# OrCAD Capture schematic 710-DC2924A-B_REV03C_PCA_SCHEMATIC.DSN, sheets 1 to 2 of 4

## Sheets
1 PAGE4: size A
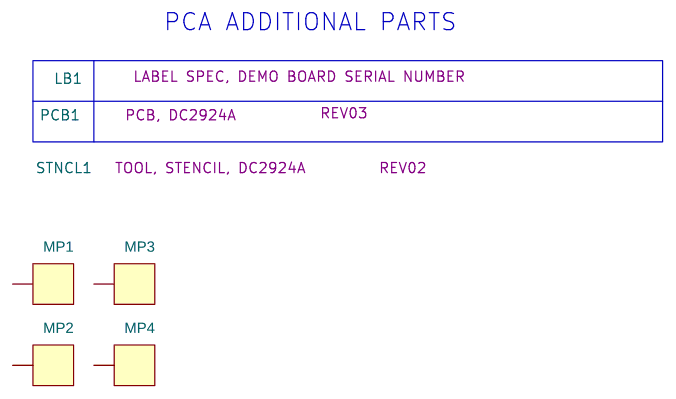
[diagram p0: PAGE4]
2 PAGE1: size Custom; title: DSP6713 SYSTEM; rev: V1.0; company: WITH DIGITAL POWER MANAGEMENT; note: 4 X 30A STEP-DOWN µMODULE SUPPLY WITH PSM
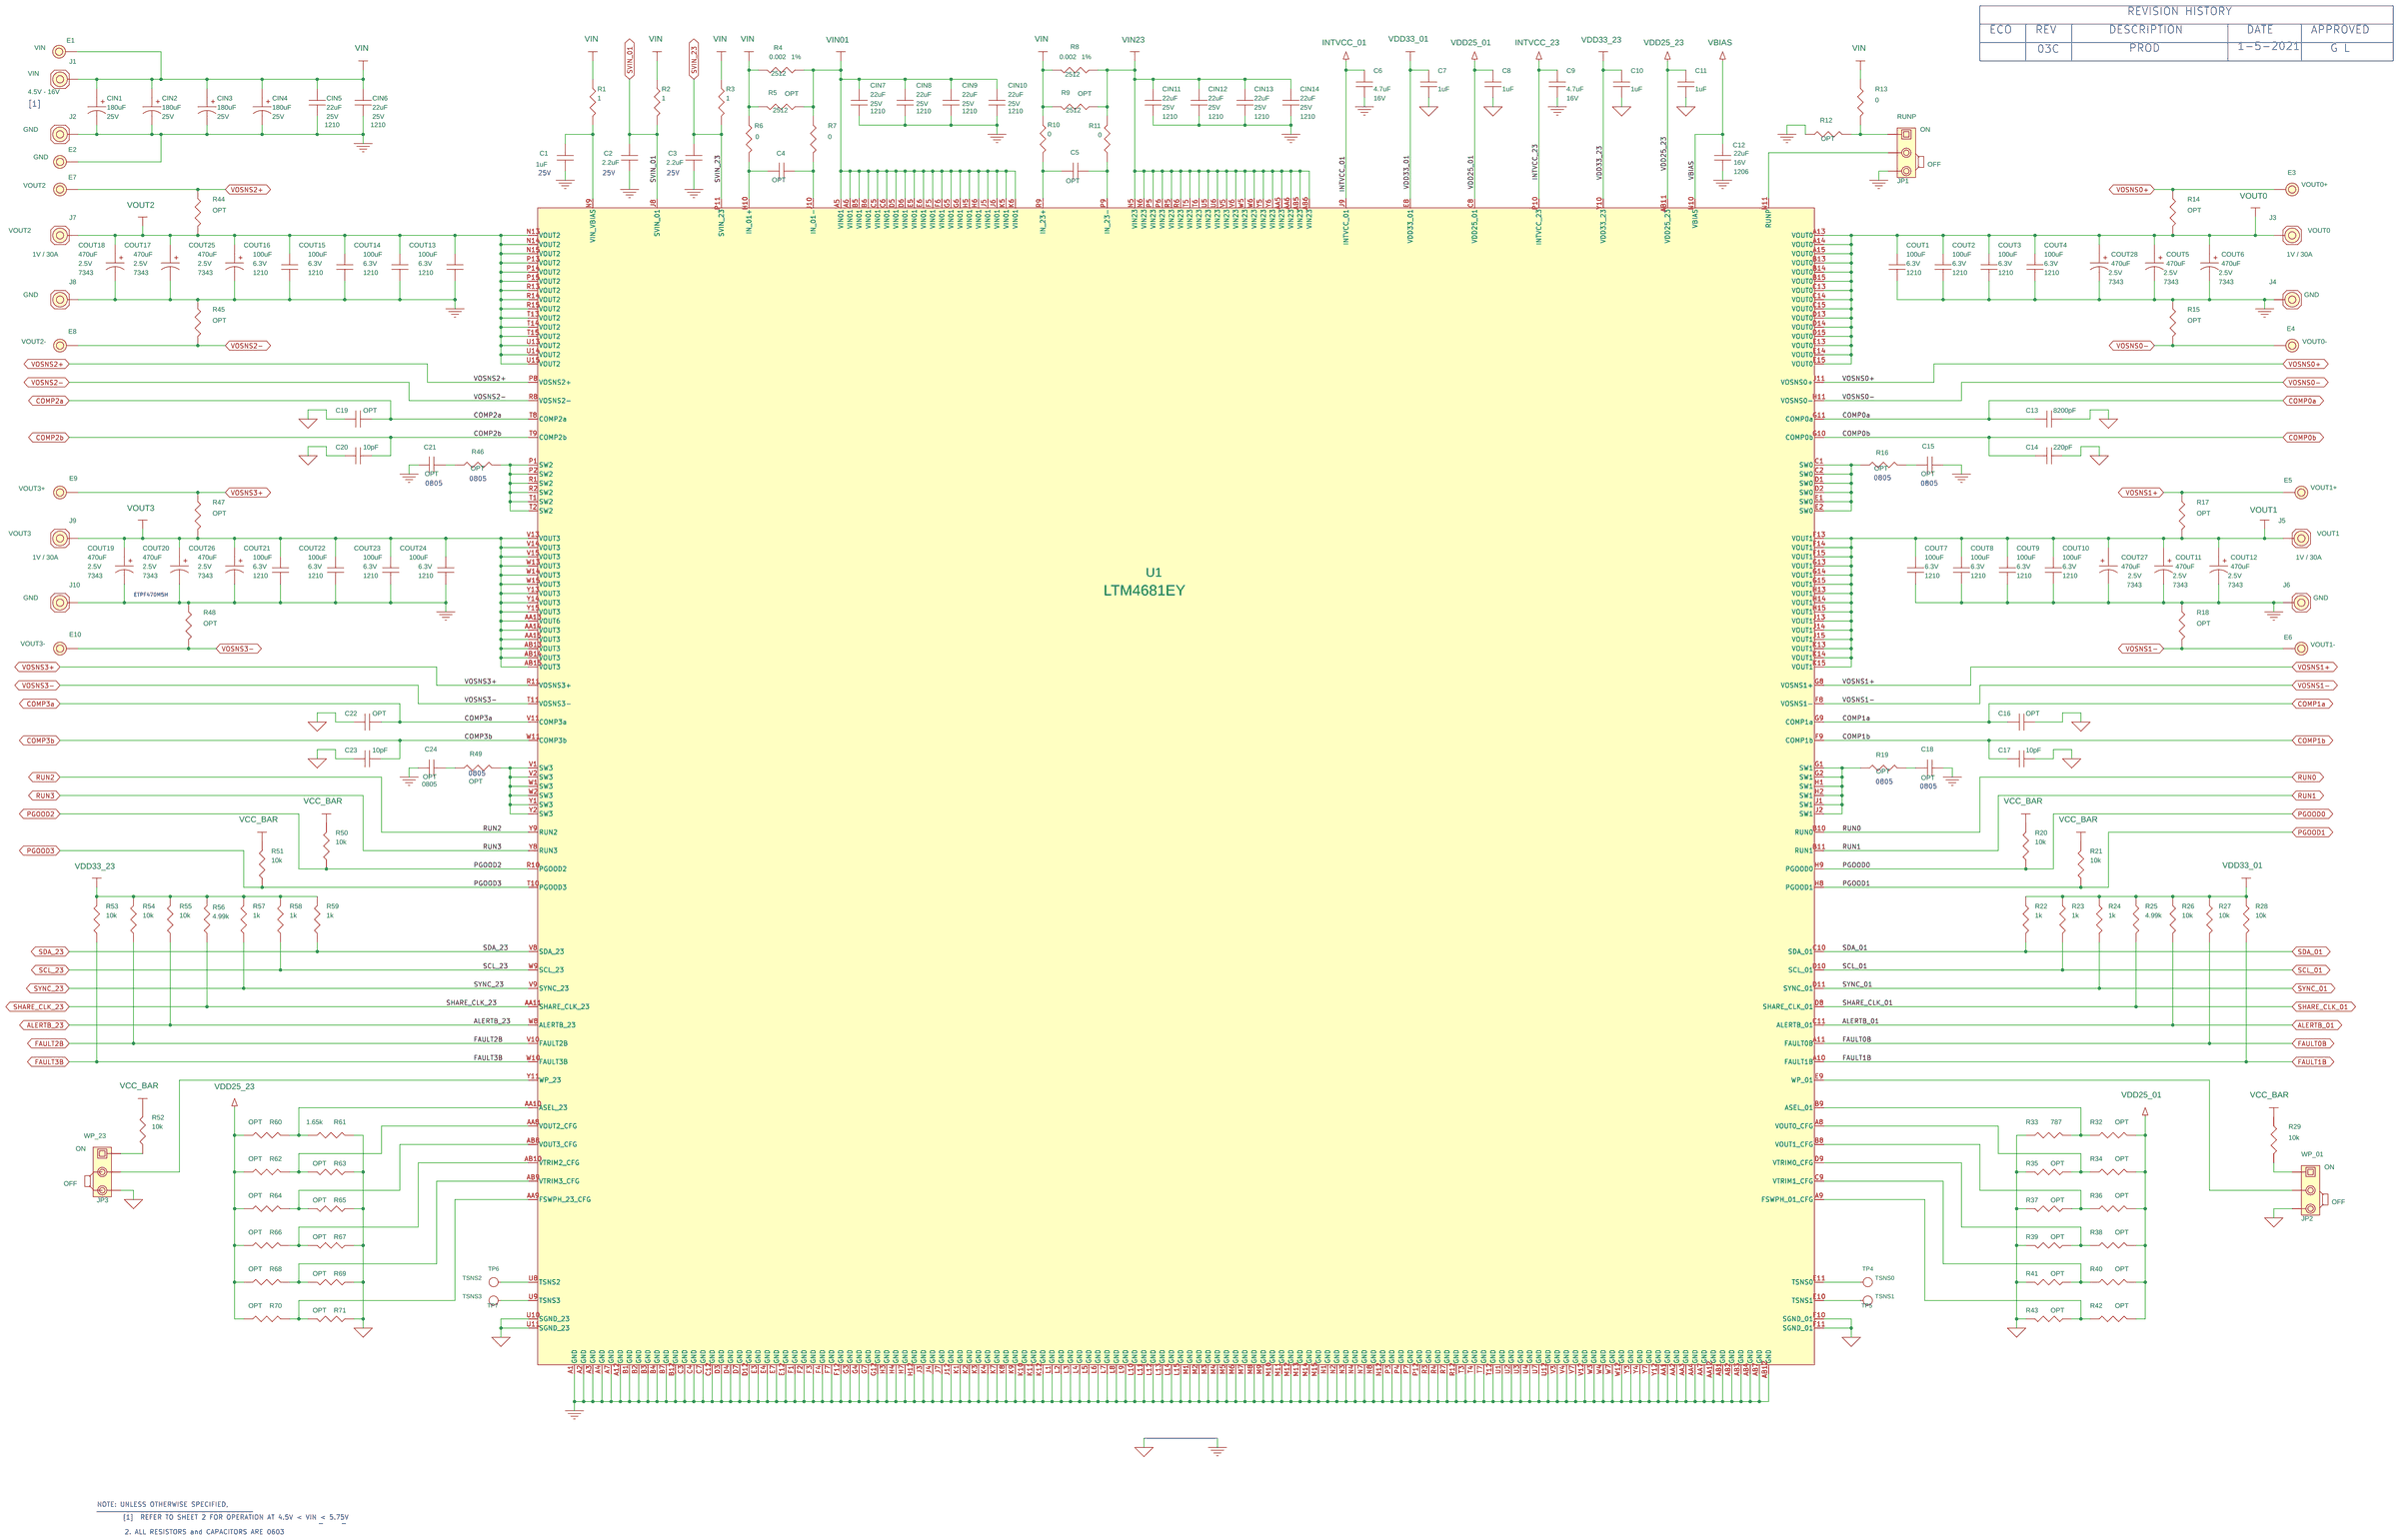
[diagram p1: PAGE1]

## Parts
sheet PAGE1
C1  1uF  [CC0603N]
C2  2.2uF  [CC0603N]
C3  2.2uF  [CC0603N]
C4  OPT  [CC0603N]
C5  OPT  [CC0603N]
C6  4.7uF  [CC0603N]
C7  1uF  [CC0603N]
C8  1uF  [CC0603N]
C9  4.7uF  [CC0603N]
C10  1uF  [CC0603N]
C11  1uF  [CC0603N]
C12  22uF  [CC1206N]
C13  8200pF  [CC0603N]
C14  220pF  [CC0603N]
C15  OPT  [CC0805N]
C16  OPT  [CC0603N]
C17  10pF  [CC0603N]
C18  OPT  [CC0805N]
C19  OPT  [CC0603N]
C20  10pF  [CC0603N]
C21  OPT  [CC0805N]
C22  OPT  [CC0603N]
C23  10pF  [CC0603N]
C24  OPT  [CC0805N]
CIN1  180uF  [PANASONIC_SVPF_8X11.9]
CIN2  180uF  [PANASONIC_SVPF_8X11.9]
CIN3  180uF  [PANASONIC_SVPF_8X11.9]
CIN4  180uF  [PANASONIC_SVPF_8X11.9]
CIN5  22uF  [CC1210N]
CIN6  22uF  [CC1210N]
CIN7  22uF  [CC1210N]
CIN8  22uF  [CC1210N]
CIN9  22uF  [CC1210N]
CIN10  22uF  [CC1210N]
CIN11  22uF  [CC1210N]
CIN12  22uF  [CC1210N]
CIN13  22uF  [CC1210N]
CIN14  22uF  [CC1210N]
COUT1  100uF  [CC1210N]
COUT2  100uF  [CC1210N]
COUT3  100uF  [CC1210N]
COUT4  100uF  [CC1210N]
COUT5  470uF  [CAPMP7343N]
COUT6  470uF  [CAPMP7343N]
COUT7  100uF  [CC1210N]
COUT8  100uF  [CC1210N]
COUT9  100uF  [CC1210N]
COUT10  100uF  [CC1210N]
COUT11  470uF  [CAPMP7343N]
COUT12  470uF  [CAPMP7343N]
COUT13  100uF  [CC1210N]
COUT14  100uF  [CC1210N]
COUT15  100uF  [CC1210N]
COUT16  100uF  [CC1210N]
COUT17  470uF  [CAPMP7343N]
COUT18  470uF  [CAPMP7343N]
COUT19  470uF  [CAPMP7343N]
COUT20  470uF  [CAPMP7343N]
COUT21  100uF  [CC1210N]
COUT22  100uF  [CC1210N]
COUT23  100uF  [CC1210N]
COUT24  100uF  [CC1210N]
COUT25  470uF  [CAPMP7343N]
COUT26  470uF  [CAPMP7343N]
COUT27  470uF  [CAPMP7343N]
COUT28  470uF  [CAPMP7343N]
E1  TEST POINT  [MILLMAX2501]
E2  TEST POINT  [MILLMAX2501]
E3  TEST POINT  [MILLMAX2501]
E4  TEST POINT  [MILLMAX2501]
E5  TEST POINT  [MILLMAX2501]
E6  TEST POINT  [MILLMAX2501]
E7  TEST POINT  [MILLMAX2501]
E8  TEST POINT  [MILLMAX2501]
E9  TEST POINT  [MILLMAX2501]
E10  TEST POINT  [MILLMAX2501]
J1  STUD,#10-32  [PENN-KFH-032]
J2  STUD,#10-32  [PENN-KFH-032]
J3  STUD,#10-32  [PENN-KFH-032]
J4  STUD,#10-32  [PENN-KFH-032]
J5  STUD,#10-32  [PENN-KFH-032]
J6  STUD,#10-32  [PENN-KFH-032]
J7  STUD,#10-32  [PENN-KFH-032]
J8  STUD,#10-32  [PENN-KFH-032]
J9  STUD,#10-32  [PENN-KFH-032]
J10  STUD,#10-32  [PENN-KFH-032]
JP1  HDR  [HD1X3-079]
JP2  HDR  [HD1X3-079]
JP3  HDR  [HD1X3-079]
R1  1  [CR0603N]
R2  1  [CR0603N]
R3  1  [CR0603N]
R4  0.002  [VISHAY-WSL2512_T87]
R5  OPT  [CR2512N]
R6  0  [CR0603N]
R7  0  [CR0603N]
R8  0.002  [VISHAY-WSL2512_T87]
R9  OPT  [CR2512N]
R10  0  [CR0603N]
R11  0  [CR0603N]
R12  OPT  [CR0603N]
R13  0  [CR0603N]
R14  OPT  [CR0603N]
R15  OPT  [CR0603N]
R16  OPT  [CR0805N]
R17  OPT  [CR0603N]
R18  OPT  [CR0603N]
R19  OPT  [CR0805N]
R20  10k  [CR0603N]
R21  10k  [CR0603N]
R22  1k  [CR0603N]
R23  1k  [CR0603N]
R24  1k  [CR0603N]
R25  4.99k  [CR0603N]
R26  10k  [CR0603N]
R27  10k  [CR0603N]
R28  10k  [CR0603N]
R29  10k  [CR0603N]
R32  OPT  [CR0603N]
R33  787  [CR0603N]
R34  OPT  [CR0603N]
R35  OPT  [CR0603N]
R36  OPT  [CR0603N]
R37  OPT  [CR0603N]
R38  OPT  [CR0603N]
R39  OPT  [CR0603N]
R40  OPT  [CR0603N]
R41  OPT  [CR0603N]
R42  OPT  [CR0603N]
R43  OPT  [CR0603N]
R44  OPT  [CR0603N]
R45  OPT  [CR0603N]
R46  OPT  [CR0805N]
R47  OPT  [CR0603N]
R48  OPT  [CR0603N]
R49  OPT  [CR0805N]
R50  10k  [CR0603N]
R51  10k  [CR0603N]
R52  10k  [CR0603N]
R53  10k  [CR0603N]
R54  10k  [CR0603N]
R55  10k  [CR0603N]
R56  4.99k  [CR0603N]
R57  1k  [CR0603N]
R58  1k  [CR0603N]
R59  1k  [CR0603N]
R60  OPT  [CR0603N]
R61  1.65k  [CR0603N]
R62  OPT  [CR0603N]
R63  OPT  [CR0603N]
R64  OPT  [CR0603N]
R65  OPT  [CR0603N]
R66  OPT  [CR0603N]
R67  OPT  [CR0603N]
R68  OPT  [CR0603N]
R69  OPT  [CR0603N]
R70  OPT  [CR0603N]
R71  OPT  [CR0603N]
TP4  TSNS0  [TP-.762MM]
TP5  TSNS1  [TP-.762MM]
TP6  TSNS2  [TP-.762MM]
TP7  TSNS3  [TP-.762MM]
U1  LTM4681EY  [LTC-BGA-330-4681Y]
XJP1  SHUNT
XJP2  SHUNT
XJP3  SHUNT
sheet PAGE4
LB1  LABEL  [895-0154_REV01]
MP1  STANDOFF  [KEYSTONE_8829-8834]
MP2  STANDOFF  [KEYSTONE_8829-8834]
MP3  STANDOFF  [KEYSTONE_8829-8834]
MP4  STANDOFF  [KEYSTONE_8829-8834]
PCB1  PCB, DC2924A
STNCL1  TOOL, STENCIL, DC2924A

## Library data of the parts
C1 C7 C8 C10 C11 = CAP: CAP.,1uF,X7R,25V,10%,0603,AEC-Q200; CLASS: DISCRETE; Dielectric Type: X7R; FPLIST: CC0603N,CC0603L,CC0603M; Inventory Qty: 53700; Manufacturer: MURATA; Manufacturer PN: GCM188R71E105KA64D; PART_NUMBER: 150-0291; Package Size: 0603; Rated Voltage: 25V; Tolerance: 10%
C2 C3 = CAP: CAP.,2.2uF,X5R,25V,10%,0603; CLASS: DISCRETE; Dielectric Type: X5R; FPLIST: CC0603N,CC0603L,CC0603M; Inventory Qty: 35022; Manufacturer: MURATA; Manufacturer PN: GRM188R61E225KA12D; PART_NUMBER: 150-3289; Package Size: 0603; Rated Voltage: 25V; Tolerance: 10%
C4 C5 C16 C19 C22 = CAP: CAP., OPTION, 0603; CLASS: DISCRETE; FPLIST: CC0603N,CC0603L,CC0603M; PART_NUMBER: 150-3038; Package Size: 0603; Package Type: SMD
C6 C9 = CAP: CAP.,4.7uF,X5R,16V,10%,0603; CLASS: DISCRETE; Dielectric Type: X5R; FPLIST: CC0603N,CC0603L,CC0603M; Inventory Qty: 44050; Manufacturer: MURATA; Manufacturer PN: GRM188R61C475KAAJD; PART_NUMBER: 150-3182; Package Size: 0603; Rated Voltage: 16V; Tolerance: 10%
C12 = CAP: CAP.,22uF,X5R,16V,10%,1206; CLASS: DISCRETE; Dielectric Type: X5R; FPLIST: CC1206N,CC1206L,CC1206M; Inventory Qty: 6429; Manufacturer: AVX; Manufacturer PN: 1206YD226KAT2A; PART_NUMBER: 150-3044; Package Size: 1206; Rated Voltage: 16V; Tolerance: 10%
C13 = CAP: CAP.,8200pF,X7R,16V,5%,0603; CLASS: DISCRETE; Dielectric Type: X7R; FPLIST: CC0603N,CC0603L,CC0603M; Inventory Qty: 4000; Manufacturer: AVX; Manufacturer PN: 0603YC822JAT2A; PART_NUMBER: 150-1315; Package Size: 0603; Rated Voltage: 16V; Tolerance: 5%
C14 = CAP: CAP.,220pF,X7R,50V,5%,0603; CLASS: DISCRETE; Dielectric Type: X7R; FPLIST: CC0603N,CC0603L,CC0603M; Inventory Qty: 0; Manufacturer: KEMET; Manufacturer PN: C0603C221J5RAC7867; PART_NUMBER: 150-0043; Package Size: 0603; Rated Voltage: 50V; Tolerance: 5%
C15 C18 C21 C24 = CAP: CAP., OPTION, 0805; CLASS: DISCRETE; FPLIST: CC0805N,CC0805L,CC0805M; PART_NUMBER: 150-3036; Package Size: 0805; Package Type: SMD
C17 C20 C23 = CAP: CAP.,10pF,C0G,50V,5%,0603; CLASS: DISCRETE; Dielectric Type: C0G; FPLIST: CC0603N,CC0603L,CC0603M; Inventory Qty: 6220; Manufacturer: AVX; Manufacturer PN: 06035A100JAT2A; PART_NUMBER: 150-0023; Package Size: 0603; Rated Voltage: 50V; Tolerance: 5%
CIN1-CIN4 = CAP_P_ALT: CAP.,180uF,ALUM POLY,OS-CON,25V,20%,8x11.9mm,SMD,RADIAL,E12; CLASS: DISCRETE; Dielectric Type: ALUM POLY,OS-CON; Inventory Qty: 5334; Manufacturer: PANASONIC; Manufacturer PN: 25SVPF180M; PART_NUMBER: 150-2329; Package Size: 8x11.9mm,SMD,RADIAL,E12; Rated Voltage: 25V; Tolerance: 20%
CIN5-CIN14 = CAP: CAP.,22uF,X5R,25V,10%,1210; CLASS: DISCRETE; Dielectric Type: X5R; FPLIST: CC1210N,CC1210L,CC1210M; Inventory Qty: 26336; Manufacturer: KEMET; Manufacturer PN: C1210C226K3PACTU; PART_NUMBER: 150-3033; Package Size: 1210; Package Type: SMD; Rated Voltage: 25V; Tolerance: 10%
COUT1-COUT4 COUT7-COUT10 COUT13-COUT16 COUT21-COUT24 = CAP: CAP.,100uF,X5R,6.3V,20%,1210; CLASS: DISCRETE; Dielectric Type: X5R; FPLIST: CC1210N,CC1210L,CC1210M; Inventory Qty: 50440; Manufacturer: AVX; Manufacturer PN: 12106D107MAT2A; PART_NUMBER: 150-3008; Package Size: 1210; Rated Voltage: 6.3V; Tolerance: 20%
COUT5 COUT6 COUT11 COUT12 COUT17 COUT20 COUT25-COUT28 = CAP_P_ALT: CAP.,470uF,TANT,POSCAP,2.5V,20%,7343,TPF Series; CLASS: DISCRETE; Dielectric Type: TANT,POSCAP; FPLIST: CAPMP7343N,CAPMP7343L,CAPMP7343M; Inventory Qty: 26416; Manufacturer: PANASONIC; Manufacturer PN: ETPF470M5H; PART_NUMBER: 150-2629; Package Size: 7343; Rated Voltage: 2.5V; Tolerance: 20%
COUT18 = CAP_P_ALT: CAP.,470uF,TANT,POSCAP,2.5V,20%,7343,TPF Series; CLASS: DISCRETE; Dielectric Type: TANT,POSCAP; FPLIST: CAPMP7343N,CAPMP7343L,CAPMP7343M; Inventory Qty: 26416; Manufacturer: PANASONIC; Manufacturer PN: ETPF470M5H; PART_FIELD_01: 2.5V; PART_NUMBER: 150-2629; Package Size: 7343; Rated Voltage: 2.5V; Tolerance: 20%
COUT19 = CAP_P_ALT: CAP.,470uF,TANT,POSCAP,2.5V,20%,7343,TPF Series; BOM Notes: COUT1,COUT6=6.3V; CLASS: DISCRETE; Dielectric Type: TANT,POSCAP; FPLIST: CAPMP7343N,CAPMP7343L,CAPMP7343M; Inventory Qty: 26416; Manufacturer: PANASONIC; Manufacturer PN: ETPF470M5H; PART_FIELD_01: 2.5V; PART_NUMBER: 150-2629; Package Size: 7343; Rated Voltage: 2.5V; Tolerance: 20%
E1 = TESTPOINT_.219_MILL-MAX_2501: TEST POINT,TURRET,0.094" MTG. HOLE,PCB 0.062" THK; 9th Part Field: VIN; CLASS: IO; Inventory Qty: 823526; Manufacturer: MILL-MAX; Manufacturer PN: 2501-2-00-80-00-00-07-0; PART_NUMBER: 260-0003
E2 = TESTPOINT_.219_MILL-MAX_2501: TEST POINT,TURRET,0.094" MTG. HOLE,PCB 0.062" THK; 9th Part Field: GND; CLASS: IO; Inventory Qty: 823526; Manufacturer: MILL-MAX; Manufacturer PN: 2501-2-00-80-00-00-07-0; PART_NUMBER: 260-0003
E3 = TESTPOINT_.219_MILL-MAX_2501: TEST POINT,TURRET,0.094" MTG. HOLE,PCB 0.062" THK; 5TH PART FIELD: VOUT0+; CLASS: IO; Inventory Qty: 823526; Manufacturer: MILL-MAX; Manufacturer PN: 2501-2-00-80-00-00-07-0; PART_NUMBER: 260-0003
E4 = TESTPOINT_.219_MILL-MAX_2501: TEST POINT,TURRET,0.094" MTG. HOLE,PCB 0.062" THK; 5TH PART FIELD: VOUT0-; CLASS: IO; Inventory Qty: 823526; Manufacturer: MILL-MAX; Manufacturer PN: 2501-2-00-80-00-00-07-0; PART_NUMBER: 260-0003
E5 = TESTPOINT_.219_MILL-MAX_2501: TEST POINT,TURRET,0.094" MTG. HOLE,PCB 0.062" THK; 9th Part Field: VOUT1+; CLASS: IO; Inventory Qty: 823526; Manufacturer: MILL-MAX; Manufacturer PN: 2501-2-00-80-00-00-07-0; PART_NUMBER: 260-0003
E6 = TESTPOINT_.219_MILL-MAX_2501: TEST POINT,TURRET,0.094" MTG. HOLE,PCB 0.062" THK; 9th Part Field: VOUT1-; CLASS: IO; Inventory Qty: 823526; Manufacturer: MILL-MAX; Manufacturer PN: 2501-2-00-80-00-00-07-0; PART_NUMBER: 260-0003
E7 = TESTPOINT_.219_MILL-MAX_2501: TEST POINT,TURRET,0.094" MTG. HOLE,PCB 0.062" THK; 9th Part Field: VOUT2; CLASS: IO; Inventory Qty: 823526; Manufacturer: MILL-MAX; Manufacturer PN: 2501-2-00-80-00-00-07-0; PART_NUMBER: 260-0003
E8 = TESTPOINT_.219_MILL-MAX_2501: TEST POINT,TURRET,0.094" MTG. HOLE,PCB 0.062" THK; 9th Part Field: VOUT2-; CLASS: IO; Inventory Qty: 823526; Manufacturer: MILL-MAX; Manufacturer PN: 2501-2-00-80-00-00-07-0; PART_NUMBER: 260-0003
E9 = TESTPOINT_.219_MILL-MAX_2501: TEST POINT,TURRET,0.094" MTG. HOLE,PCB 0.062" THK; 9th Part Field: VOUT3+; CLASS: IO; Inventory Qty: 823526; Manufacturer: MILL-MAX; Manufacturer PN: 2501-2-00-80-00-00-07-0; PART_NUMBER: 260-0003
E10 = TESTPOINT_.219_MILL-MAX_2501: TEST POINT,TURRET,0.094" MTG. HOLE,PCB 0.062" THK; 9th Part Field: VOUT3-; CLASS: IO; Inventory Qty: 823526; Manufacturer: MILL-MAX; Manufacturer PN: 2501-2-00-80-00-00-07-0; PART_NUMBER: 260-0003
J1 = PEM-KFH: EVAL BOARD STUD HARDWARE SET, #10-32; 10th Part Field: 4.5V - 16V; 9th Part Field: VIN; CLASS: DISCRETE; Comments: CONSISTS OF QTY(1) STUD, 769-0012; QTY(1) RING LUG, 769-0013;QTY(2) HEX NUT,BRASS,761-0013; QTY(1) WASHER,#10 LOCK, 762-0021; Manufacturer: ANALOG DEVICES; Manufacturer PN: 720-0010; PART_NUMBER: 720-0010
J2 J4 J6 J8 J10 = PEM-KFH: EVAL BOARD STUD HARDWARE SET, #10-32; 9th Part Field: GND; CLASS: DISCRETE; Comments: CONSISTS OF QTY(1) STUD, 769-0012; QTY(1) RING LUG, 769-0013;QTY(2) HEX NUT,BRASS,761-0013; QTY(1) WASHER,#10 LOCK, 762-0021; Manufacturer: ANALOG DEVICES; Manufacturer PN: 720-0010; PART_NUMBER: 720-0010
J3 = PEM-KFH: EVAL BOARD STUD HARDWARE SET, #10-32; 10th Part Field: 1V / 30A; 9th Part Field: VOUT0; CLASS: DISCRETE; Comments: CONSISTS OF QTY(1) STUD, 769-0012; QTY(1) RING LUG, 769-0013;QTY(2) HEX NUT,BRASS,761-0013; QTY(1) WASHER,#10 LOCK, 762-0021; Manufacturer: ANALOG DEVICES; Manufacturer PN: 720-0010; PART_NUMBER: 720-0010
J5 = PEM-KFH: EVAL BOARD STUD HARDWARE SET, #10-32; 10th Part Field: 1V / 30A; 9th Part Field: VOUT1; CLASS: DISCRETE; Comments: CONSISTS OF QTY(1) STUD, 769-0012; QTY(1) RING LUG, 769-0013;QTY(2) HEX NUT,BRASS,761-0013; QTY(1) WASHER,#10 LOCK, 762-0021; Manufacturer: ANALOG DEVICES; Manufacturer PN: 720-0010; PART_NUMBER: 720-0010
J7 = PEM-KFH: EVAL BOARD STUD HARDWARE SET, #10-32; 10th Part Field: 1V / 30A; 9th Part Field: VOUT2; CLASS: DISCRETE; Comments: CONSISTS OF QTY(1) STUD, 769-0012; QTY(1) RING LUG, 769-0013;QTY(2) HEX NUT,BRASS,761-0013; QTY(1) WASHER,#10 LOCK, 762-0021; Manufacturer: ANALOG DEVICES; Manufacturer PN: 720-0010; PART_NUMBER: 720-0010
J9 = PEM-KFH: EVAL BOARD STUD HARDWARE SET, #10-32; 10th Part Field: 1V / 30A; 9th Part Field: VOUT3; CLASS: DISCRETE; Comments: CONSISTS OF QTY(1) STUD, 769-0012; QTY(1) RING LUG, 769-0013;QTY(2) HEX NUT,BRASS,761-0013; QTY(1) WASHER,#10 LOCK, 762-0021; Manufacturer: ANALOG DEVICES; Manufacturer PN: 720-0010; PART_NUMBER: 720-0010
JP1 = 1X3_A: CONN.,HDR,MALE,1x3,2mm,VERT,ST,THT,NO SUBS. ALLOWED; 11th Part Field: OFF; 12th Part Field: RUNP; 9th Part Field: ON; CLASS: IO; Inventory Qty: 28997; Manufacturer: Wurth Elektronik; Manufacturer PN: 62000311121; PART_NUMBER: 250-0639
JP2 = 1X3_A: CONN.,HDR,MALE,1x3,2mm,VERT,ST,THT,NO SUBS. ALLOWED; 11th Part Field: OFF; 12th Part Field: WP_01; 9th Part Field: ON; CLASS: IO; Inventory Qty: 28997; Manufacturer: Wurth Elektronik; Manufacturer PN: 62000311121; PART_NUMBER: 250-0639
JP3 = 1X3_A: CONN.,HDR,MALE,1x3,2mm,VERT,ST,THT,NO SUBS. ALLOWED; 11th Part Field: OFF; 12th Part Field: WP_23; 9th Part Field: ON; CLASS: IO; Inventory Qty: 28997; Manufacturer: Wurth Elektronik; Manufacturer PN: 62000311121; PART_NUMBER: 250-0639
R1-R3 = RES: RES.,1 OHM,1%,1/10W,0603,AEC-Q200; CLASS: DISCRETE; FPLIST: CR0603N,CR0603L,CR0603M; Inventory Qty: 53360; Manufacturer: NIC; Manufacturer PN: NRC06F1R00TRF; PART_NUMBER: 100-0238; Package Size: 0603; Rated Power: 1/10W; Temperature Coefficient: 100ppm/C; Tolerance: 1%
R4 R8 = RES: RES.,0.002 OHM,1%,1W,2512,SENSE; CLASS: DISCRETE; FPLIST: CR2512N,CR2512L,CR2512M; Inventory Qty: 9849; Manufacturer: VISHAY; Manufacturer PN: WSL25122L000FEA; PART_NUMBER: 100-0062; Package Size: 2512; Rated Power: 1W; Temperature Coefficient: 275ppm/C; Tolerance: 1%
R5 R9 = RES: RES., OPTION, 2512; CLASS: DISCRETE; FPLIST: CR2512N,CR2512L,CR2512M,USER_ASSIGNED; PART_NUMBER: 100-2376; Package Size: 2512
R6 R7 R10 R11 R13 = RES: RES.,0 OHM,1/10W,0603,AEC-Q200; CLASS: DISCRETE; FPLIST: CR0603N,CR0603L,CR0603M; Inventory Qty: 700742; Manufacturer: VISHAY; Manufacturer PN: CRCW06030000Z0EA; PART_NUMBER: 100-0009; Package Size: 0603; Rated Power: 1/10W
R12 R14 R15 R17 R18 R32 R34-R45 R47 R48 R60 R62-R71 = RES: RES., OPTION, 0603; CLASS: DISCRETE; FPLIST: CR0603N,CR0603L,CR0603M; PART_NUMBER: 100-2374; Package Size: 0603
R16 R19 R46 R49 = RES: RES., OPTION, 0805; CLASS: DISCRETE; FPLIST: CR0805N,CR0805L,CR0805M; PART_NUMBER: 100-2558; Package Size: 0805
R20 R21 R26-R29 R50-R55 = RES: RES.,10k OHMS,1%,1/10W,0603,AEC-Q200; CLASS: DISCRETE; FPLIST: CR0603N,CR0603L,CR0603M; Inventory Qty: 194448; Manufacturer: VISHAY; Manufacturer PN: CRCW060310K0FKEA; PART_NUMBER: 100-2012; Package Size: 0603; Rated Power: 1/10W; Temperature Coefficient: +/-100ppm/C; Tolerance: 1%
R22-R24 R57-R59 = RES: RES.,1k OHM,1%,1/10W,0603; CLASS: DISCRETE; FPLIST: CR0603N,CR0603L,CR0603M; Inventory Qty: 62420; Manufacturer: VISHAY; Manufacturer PN: CRCW06031K00FKEA; PART_NUMBER: 100-0136; Package Size: 0603; Rated Power: 1/10W; Temperature Coefficient: +/-100ppm; Tolerance: 1%
R25 R56 = RES: RES.,4.99k OHMS,1%,1/10W,0603; CLASS: DISCRETE; FPLIST: CR0603N,CR0603L,CR0603M; Inventory Qty: 72747; Manufacturer: PANASONIC; Manufacturer PN: ERJ3EKF4991V; PART_NUMBER: 100-0121; Package Size: 0603; Rated Power: 1/10W; Temperature Coefficient: 100ppm/C; Tolerance: 1%
R33 = RES: RES.,787 OHMS,1%,1/10W,0603; CLASS: DISCRETE; FPLIST: CR0603N,CR0603L,CR0603M; Inventory Qty: 19395; Manufacturer: NIC; Manufacturer PN: NRC06F7870TRF; PART_NUMBER: 100-2721; Package Size: 0603; Rated Power: 1/10W; Temperature Coefficient: 100ppm/C; Tolerance: 1%
R61 = RES: RES.,1.65k OHMS,1%,1/10W,0603; CLASS: DISCRETE; FPLIST: CR0603N,CR0603L,CR0603M; Inventory Qty: 27055; Manufacturer: NIC; Manufacturer PN: NRC06F1651TRF; PART_NUMBER: 100-2723; Package Size: 0603; Rated Power: 1/10W; Temperature Coefficient: 100ppm/C; Tolerance: 1%
TP4-TP7 = E-100SMT
U1 = LTM4681-BGA: IC,QUAD OUTPUT uMODULE REG.,BGA; CLASS: IC; Inventory Qty: 0; Manufacturer: ANALOG DEVICES; Manufacturer PN: LTM4681EY#PBF; PART_NUMBER: LTM4681EY#PBF; Package Type: BGA
XJP1-XJP3 = SHUNT_2MM: CONN.,SHUNT,FEMALE,2 POS,2mm; CLASS: IO; Inventory Qty: 64675; Manufacturer: Wurth Elektronik; Manufacturer PN: 60800213421; PART_NUMBER: 250-0485
LB1 = BLANK_LABEL: LABEL SPEC, DEMO BOARD SERIAL NUMBER; Inventory Qty: 0; Manufacturer: BRADY; Manufacturer PN: THT-96-717-10; PART_NUMBER: 895-0154
MP1-MP4 = MP-PINNED: STANDOFF,NYLON,SNAP-ON,0.50"; CLASS: DISCRETE; FPLIST: KEYSTONE_8829-8834,KEYSTONE_8833,MTG-8831; Inventory Qty: 214842; Manufacturer: KEYSTONE; Manufacturer PN: 8833; PART_NUMBER: 763-0007
PCB1 = BLANK_PCB_PART: BOM Notes: REV03; CLASS: DISCRETE; Inventory Qty: 0; Manufacturer: ADI APPROVED SUPPLIER; Manufacturer PN: 600-DC2924A; PART_NUMBER: 600-DC2924A
STNCL1 = BLANK_STENCIL_PART: BOM Notes: REV02; CLASS: DISCRETE; Inventory Qty: 0; Manufacturer: ANALOG DEVICES; Manufacturer PN: 830-DC2924A; PART_NUMBER: 830-DC2924A

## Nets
GND: C1.1 C2.1 C3.1 C6.1 C9.1 C12.1 C15.1 C18.1 C21.1 C24.1 CIN1.2 CIN2.2 CIN3.2 CIN4.2 CIN5.1 CIN6.1 CIN7.1 CIN8.1 CIN9.1 CIN10.1 CIN11.1 CIN12.1 CIN13.1 CIN14.1 COUT1.2 COUT2.2 COUT3.2 COUT4.2 COUT5.2 COUT6.2 COUT7.2 COUT8.2 COUT9.2 COUT10.2 COUT11.2 COUT12.2 COUT13.2 COUT14.2 COUT15.2 COUT16.2 COUT17.2 COUT18.2 COUT19.2 COUT20.2 COUT21.2 COUT22.2 COUT23.2 COUT24.2 COUT25.2 COUT26.2 COUT27.2 COUT28.2 E2.1 J2.1 J4.1 J6.1 J8.1 J10.1 JP1.3 R12.1 R15.1 R18.1 R45.1 R48.1 U1.A1(GND) U1.A2(GND) U1.A3(GND) U1.A4(GND) U1.A7(GND) U1.A12(GND) U1.AA1(GND) U1.AA2(GND) U1.AA3(GND) U1.AA4(GND) U1.AA7(GND) U1.AA12(GND) U1.AB1(GND) U1.AB2(GND) U1.AB3(GND) U1.AB4(GND) U1.AB7(GND) U1.AB12(GND) U1.B1(GND) U1.B2(GND) U1.B3(GND) U1.B4(GND) U1.B7(GND) U1.B12(GND) U1.C3(GND) U1.C4(GND) U1.C7(GND) U1.C12(GND) U1.D3(GND) U1.D4(GND) U1.D7(GND) U1.D12(GND) U1.E3(GND) U1.E4(GND) U1.E7(GND) U1.E12(GND) U1.F1(GND) U1.F2(GND) U1.F3(GND) U1.F4(GND) U1.F7(GND) U1.F12(GND) U1.G3(GND) U1.G4(GND) U1.G7(GND) U1.G12(GND) U1.H3(GND) U1.H4(GND) U1.H7(GND) U1.H12(GND) U1.J3(GND) U1.J4(GND) U1.J7(GND) U1.J12(GND) U1.K1(GND) U1.K2(GND) U1.K3(GND) U1.K4(GND) U1.K7(GND) U1.K8(GND) U1.K9(GND) U1.K10(GND) U1.K11(GND) U1.K12(GND) U1.L1(GND) U1.L2(GND) U1.L3(GND) U1.L4(GND) U1.L5(GND) U1.L6(GND) U1.L7(GND) U1.L8(GND) U1.L9(GND) U1.L10(GND) U1.L11(GND) U1.L12(GND) U1.L13(GND) U1.L14(GND) U1.L15(GND) U1.M1(GND) U1.M2(GND) U1.M3(GND) U1.M4(GND) U1.M5(GND) U1.M6(GND) U1.M7(GND) U1.M8(GND) U1.M9(GND) U1.M10(GND) U1.M11(GND) U1.M12(GND) U1.M13(GND) U1.M14(GND) U1.M15(GND) U1.N1(GND) U1.N2(GND) U1.N3(GND) U1.N4(GND) U1.N7(GND) U1.N8(GND) U1.N12(GND) U1.P3(GND) U1.P4(GND) U1.P7(GND) U1.P12(GND) U1.R3(GND) U1.R4(GND) U1.R7(GND) U1.R12(GND) U1.T3(GND) U1.T4(GND) U1.T7(GND) U1.T12(GND) U1.U1(GND) U1.U2(GND) U1.U3(GND) U1.U4(GND) U1.U7(GND) U1.U12(GND) U1.V3(GND) U1.V4(GND) U1.V7(GND) U1.V12(GND) U1.W3(GND) U1.W4(GND) U1.W7(GND) U1.W12(GND) U1.Y3(GND) U1.Y4(GND) U1.Y7(GND) U1.Y12(GND) ; also on sheet 3 4
GND_SIGNAL: C7.1 C8.1 C10.1 C11.1 C13.1 C14.1 C16.1 C17.1 C19.1 C20.1 C22.1 C23.1 JP2.3 JP3.3 R33.1 R35.1 R37.1 R39.1 R41.1 R43.1 R61.1 R63.1 R65.1 R67.1 R69.1 R71.1 U1.F10(SGND_01) U1.F11(SGND_01) U1.U10(SGND_23) U1.U11(SGND_23) ; also on sheet 3
SVIN_01: C2.2 R2.2 U1.J8(SVIN_01) ; also on sheet 3
SVIN_23: C3.2 R3.2 U1.P11(SVIN_23) ; also on sheet 3
VDD25_01: C8.2 R32.2 R34.2 R36.2 R38.2 R40.2 R42.2 U1.C8(VDD25_01) ; also on sheet 3
VDD25_23: C11.2 R60.2 R62.2 R64.2 R66.2 R68.2 R70.2 U1.AB11(VDD25_23) ; also on sheet 3
VDD33_01: C7.2 R20.2 R21.2 R22.1 R23.1 R24.1 R25.1 R26.1 R27.1 R28.1 R29.1 U1.E8(VDD33_01) ; also on sheet 3 4
VDD33_23: C10.2 R50.2 R51.2 R52.1 R53.1 R54.1 R55.1 R56.1 R57.1 R58.1 R59.1 U1.Y10(VDD33_23) ; also on sheet 3 4
VIN: CIN1.1 CIN2.1 CIN3.1 CIN4.1 CIN5.2 CIN6.2 E1.1 J1.1 R1.1 R2.1 R3.1 R4.1 R5.1 R6.1 R8.1 R9.1 R10.1 R13.1 ; also on sheet 3 4
VIN01: CIN7.2 CIN8.2 CIN9.2 CIN10.2 R4.2 R5.2 R7.1 U1.A5(VIN01) U1.A6(VIN01) U1.B5(VIN01) U1.B6(VIN01) U1.C5(VIN01) U1.C6(VIN01) U1.D5(VIN01) U1.D6(VIN01) U1.E5(VIN01) U1.E6(VIN01) U1.F5(VIN01) U1.F6(VIN01) U1.G5(VIN01) U1.G6(VIN01) U1.H5(VIN01) U1.H6(VIN01) U1.J5(VIN01) U1.J6(VIN01) U1.K5(VIN01) U1.K6(VIN01)
VIN23: CIN11.2 CIN12.2 CIN13.2 CIN14.2 R8.2 R9.2 R11.1 U1.AA5(VIN23) U1.AA6(VIN23) U1.AB5(VIN23) U1.AB6(VIN23) U1.N5(VIN23) U1.N6(VIN23) U1.P5(VIN23) U1.P6(VIN23) U1.R5(VIN23) U1.R6(VIN23) U1.T5(VIN23) U1.T6(VIN23) U1.U5(VIN23) U1.U6(VIN23) U1.V5(VIN23) U1.V6(VIN23) U1.W5(VIN23) U1.W6(VIN23) U1.Y5(VIN23) U1.Y6(VIN23)
ALERTB_01: R26.2 U1.C11(ALERTB_01) ; also on sheet 3 4
ALERTB_23: R55.2 U1.W8(ALERTB_23) ; also on sheet 3 4
COMP0a: C13.2 U1.G11(COMP0a) ; also on sheet 3
COMP0b: C14.2 U1.G10(COMP0b) ; also on sheet 3
COMP1a: C16.2 U1.G9(COMP1a) ; also on sheet 3
COMP1b: C17.2 U1.F9(COMP1b) ; also on sheet 3
COMP2a: C19.2 U1.T8(COMP2a) ; also on sheet 3
COMP2b: C20.2 U1.T9(COMP2b) ; also on sheet 3
COMP3a: C22.2 U1.V11(COMP3a) ; also on sheet 3
COMP3b: C23.2 U1.W11(COMP3b) ; also on sheet 3
FAULT0B: R27.2 U1.A11(FAULT0B) ; also on sheet 3 4
FAULT1B: R28.2 U1.A10(FAULT1B) ; also on sheet 3 4
FAULT2B: R54.2 U1.V10(FAULT2B) ; also on sheet 3 4
FAULT3B: R53.2 U1.W10(FAULT3B) ; also on sheet 3 4
INTVCC_01: C6.2 U1.J9(INTVCC_01) ; also on sheet 3
INTVCC_23: C9.2 U1.P10(INTVCC_23) ; also on sheet 3
PGOOD0: R20.1 U1.H9(PGOOD0) ; also on sheet 3
PGOOD1: R21.1 U1.H8(PGOOD1) ; also on sheet 3
PGOOD2: R50.1 U1.R10(PGOOD2) ; also on sheet 3
PGOOD3: R51.1 U1.T10(PGOOD3) ; also on sheet 3
RUN0: U1.B10(RUN0) ; also on sheet 3 4
RUN1: U1.B11(RUN1) ; also on sheet 3 4
RUN2: U1.Y9(RUN2) ; also on sheet 3 4
RUN3: U1.Y8(RUN3) ; also on sheet 3 4
SCL_01: R23.2 U1.D10(SCL_01) ; also on sheet 4
SCL_23: R58.2 U1.W9(SCL_23) ; also on sheet 4
SDA_01: R22.2 U1.C10(SDA_01) ; also on sheet 4
SDA_23: R59.2 U1.V8(SDA_23) ; also on sheet 4
SHARE_CLK_01: R25.2 U1.D8(SHARE_CLK_01) ; also on sheet 4
SHARE_CLK_23: R56.2 U1.AA11(SHARE_CLK_23) ; also on sheet 4
SYNC_01: R24.2 U1.D11(SYNC_01) ; also on sheet 4
SYNC_23: R57.2 U1.V9(SYNC_23) ; also on sheet 4
VBIAS: C12.2 U1.N10(VBIAS) ; also on sheet 3
VOSNS0+: E3.1 R14.1 U1.J11(VOSNS0+) ; also on sheet 3
VOSNS0-: E4.1 R15.2 U1.H11(VOSNS0-) ; also on sheet 3
VOSNS1+: E5.1 R17.1 U1.G8(VOSNS1+) ; also on sheet 3
VOSNS1-: E6.1 R18.2 U1.F8(VOSNS1-) ; also on sheet 3
VOSNS2+: E7.1 R44.1 U1.P8(VOSNS2+) ; also on sheet 3
VOSNS2-: E8.1 R45.2 U1.R8(VOSNS2-) ; also on sheet 3
VOSNS3+: E9.1 R47.1 U1.R11(VOSNS3+) ; also on sheet 3
VOSNS3-: E10.1 R48.2 U1.T11(VOSNS3-) ; also on sheet 3
VOUT0: COUT1.1 COUT2.1 COUT3.1 COUT4.1 COUT5.1 COUT6.1 COUT28.1 J3.1 R14.2 U1.A13(VOUT0) U1.A14(VOUT0) U1.A15(VOUT0) U1.B13(VOUT0) U1.B14(VOUT0) U1.B15(VOUT0) U1.C13(VOUT0) U1.C14(VOUT0) U1.C15(VOUT0) U1.D13(VOUT0) U1.D14(VOUT0) U1.D15(VOUT0) U1.E13(VOUT0) U1.E14(VOUT0) U1.E15(VOUT0) ; also on sheet 3
VOUT1: COUT7.1 COUT8.1 COUT9.1 COUT10.1 COUT11.1 COUT12.1 COUT27.1 J5.1 R17.2 U1.F13(VOUT1) U1.F14(VOUT1) U1.F15(VOUT1) U1.G13(VOUT1) U1.G14(VOUT1) U1.G15(VOUT1) U1.H13(VOUT1) U1.H14(VOUT1) U1.H15(VOUT1) U1.J13(VOUT1) U1.J14(VOUT1) U1.J15(VOUT1) U1.K13(VOUT1) U1.K14(VOUT1) U1.K15(VOUT1) ; also on sheet 3
VOUT2: COUT13.1 COUT14.1 COUT15.1 COUT16.1 COUT17.1 COUT18.1 COUT25.1 J7.1 R44.2 U1.N13(VOUT2) U1.N14(VOUT2) U1.N15(VOUT2) U1.P13(VOUT2) U1.P14(VOUT2) U1.P15(VOUT2) U1.R13(VOUT2) U1.R14(VOUT2) U1.R15(VOUT2) U1.T13(VOUT2) U1.T14(VOUT2) U1.T15(VOUT2) U1.U13(VOUT2) U1.U14(VOUT2) U1.U15(VOUT2) ; also on sheet 3
VOUT3: COUT19.1 COUT20.1 COUT21.1 COUT22.1 COUT23.1 COUT24.1 COUT26.1 J9.1 R47.2 U1.AA13(VOUT6) U1.AA14(VOUT3) U1.AA15(VOUT3) U1.AB13(VOUT3) U1.AB14(VOUT3) U1.AB15(VOUT3) U1.V13(VOUT3) U1.V14(VOUT3) U1.V15(VOUT3) U1.W13(VOUT3) U1.W14(VOUT3) U1.W15(VOUT3) U1.Y13(VOUT3) U1.Y14(VOUT3) U1.Y15(VOUT3) ; also on sheet 3
N21382349: C1.2 R1.2 U1.N9(VIN_VBIAS)
N21389813: C4.2 R6.2 U1.H10(IN_01+)
N21389816: C4.1 R7.2 U1.J10(IN_01-)
N21395875: C5.2 R10.2 U1.R9(IN_23+)
N21395885: C5.1 R11.2 U1.P9(IN_23-)
N21431561: JP1.1 R12.2 R13.2
N21443536: JP1.2 U1.N11(RUNP)
N21472624: R16.1 U1.C1(SW0) U1.C2(SW0) U1.D1(SW0) U1.D2(SW0) U1.E1(SW0) U1.E2(SW0)
N21487261: R19.1 U1.G1(SW1) U1.G2(SW1) U1.H1(SW1) U1.H2(SW1) U1.J1(SW1) U1.J2(SW1)
N21487379: C18.2 R19.2
N21500618: JP2.2 U1.E9(WP_01)
N21504886: JP2.1 R29.2
N21515478: R34.1 R35.2 U1.A8(VOUT0_CFG)
N21517814: R36.1 R37.2 U1.B8(VOUT1_CFG)
N21517925: R38.1 R39.2 U1.D9(VTRIM0_CFG)
N21518062: R40.1 R41.2 U1.C9(VTRIM1_CFG)
N21518084: R42.1 R43.2 U1.A9(FSWPH_01_CFG)
N21518290: R32.1 R33.2 U1.B9(ASEL_01)
N21537966: TP4.1(A) U1.E11(TSNS0)
N21537986: TP5.1(A) U1.E10(TSNS1)
N21554155: R46.1 U1.P1(SW2) U1.P2(SW2) U1.R1(SW2) U1.R2(SW2) U1.T1(SW2) U1.T2(SW2)
N21563513: R49.1 U1.V1(SW3) U1.V2(SW3) U1.W1(SW3) U1.W2(SW3) U1.Y1(SW3) U1.Y2(SW3)
N21563751: C24.2 R49.2
N21568029: JP3.1 R52.2
N21569954: R60.1 R61.2 U1.AA10(ASEL_23)
N21569988: R64.1 R65.2 U1.AB8(VOUT3_CFG)
N21570008: R66.1 R67.2 U1.AB10(VTRIM2_CFG)
N21570032: R62.1 R63.2 U1.AA8(VOUT2_CFG)
N21570040: R68.1 R69.2 U1.AB9(VTRIM3_CFG)
N21570064: R70.1 R71.2 U1.AA9(FSWPH_23_CFG)
N21570170: TP6.1(A) U1.U8(TSNS2)
N21570190: TP7.1(A) U1.U9(TSNS3)
N21571790: JP3.2 U1.Y11(WP_23)
N21838591: C15.2 R16.2
N22173279: C21.2 R46.2

Not connected (* = marked no-connect by the designer): MP1 1; MP2 1; MP3 1; MP4 1

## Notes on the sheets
sheet 1
- PCA ADDITIONAL PARTS
sheet 2
- REVISION HISTORY
- ECO
- REV
- DESCRIPTION
- DATE
- APPROVED
- 1-5-2021
- 03C
- PROD
- G L
- [1]
- 25V
- 25V
- 25V
- 0805
- 0805
- 0805
- 0805
- ETPF470M5H
- 0805
- 0805
- 0805
- NOTE: UNLESS OTHERWISE SPECIFIED,
- [1]  REFER TO SHEET 2 FOR OPERATION AT 4.5V < VIN < 5.75V
- 2. ALL RESISTORS and CAPACITORS ARE 0603
